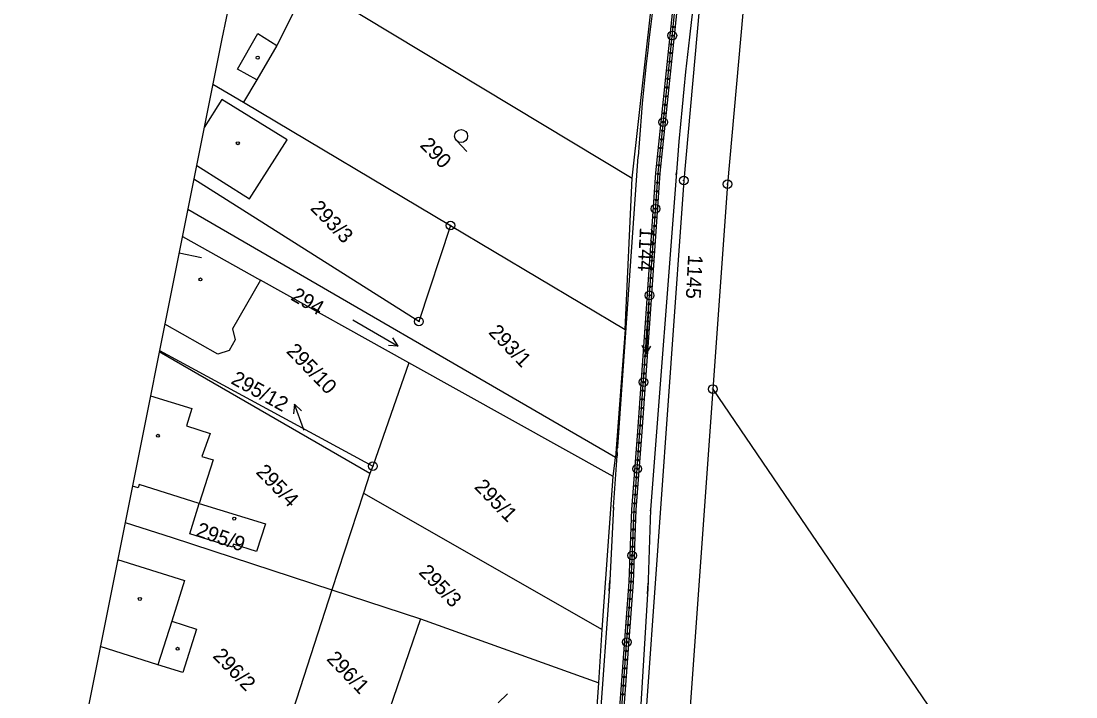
# Model space of a CAD drawing. Extents: x -548552 to -543113, y -1131925 to -1123599.
# Drawn here: x -547973.3 to -547852, y -1129232.9 to -1129155.2 of the extents above; entities that cross this region are included whole.
import ezdxf

# ---------------------------------------------------------------- set-up
doc = ezdxf.new("R2010")
doc.units = 0
for name, color, linetype in [('Hranice parcel', 7, 'Continuous'), ('Parcelní čísla', 7, 'Continuous'), ('Pop  PČ popisy', 7, 'Continuous'), ('Profile', 7, 'Continuous'), ('PROFILY NÁVRH', 7, 'Continuous'), ('STANIČENÍ', 7, 'Continuous'), ('Vnitřní kresba', 7, 'Continuous'), ('Značky bodu BP', 7, 'Continuous'), ('Značky budov', 7, 'Continuous'), ('Značky kultur', 7, 'Continuous')]:
    doc.layers.add(name, color=color, linetype=linetype)

msp = doc.modelspace()

# ---------------------------------------------------------------- linework, layer by layer
at = {"layer": 'Hranice parcel'}
for p, q in [((-547939.12, -1129151.47), (-547903.04, -1129173.24)), ((-547903.04, -1129173.24), (-547900.82, -1129153.33)), ((-547951.24, -1129162.42), (-547947.73, -1129164.51)), ((-547947.73, -1129164.51), (-547923.93, -1129178.68)), ((-547903.84, -1129190.64), (-547903.04, -1129173.24)), ((-547904.96, -1129205.36), (-547954.13, -1129176.84)), ((-547923.93, -1129178.68), (-547903.84, -1129190.64)), ((-547954.75, -1129179.95), (-547945.78, -1129184.96)), ((-547928.72, -1129194.48), (-547945.78, -1129184.96)), ((-547903.84, -1129190.64), (-547904.96, -1129205.36)), ((-547933.19, -1129207.21), (-547957.41, -1129193.21)), ((-547957.38, -1129193.07), (-547932.84, -1129206.37)), ((-547928.72, -1129194.48), (-547932.84, -1129206.37)), ((-547905.23, -1129207.58), (-547928.72, -1129194.48)), ((-547893.76, -1129197.5), (-547897.12, -1129244.73)), ((-547893.76, -1129197.5), (-547826.6, -1129296.2)), ((-547905.23, -1129207.58), (-547904.96, -1129205.36)), ((-547933.19, -1129207.21), (-547933.93, -1129209.49)), ((-547932.84, -1129206.37), (-547933.19, -1129207.21)), ((-547906.46, -1129225.18), (-547905.23, -1129207.58)), ((-547933.93, -1129209.49), (-547937.55, -1129220.62)), ((-547933.93, -1129209.49), (-547906.46, -1129225.18)), ((-547937.55, -1129220.62), (-547942.59, -1129236.09)), ((-547937.55, -1129220.62), (-547927.38, -1129223.94)), ((-547927.38, -1129223.94), (-547932.61, -1129239.25)), ((-547927.38, -1129223.94), (-547906.88, -1129231.29)), ((-547906.88, -1129231.29), (-547906.46, -1129225.18)), ((-547908.01, -1129247.43), (-547906.88, -1129231.29))]:
    msp.add_line(p, q, dxfattribs=at)
for points in [[(-547821.33, -1128991.6), (-547858.78, -1129039.17), (-547867.17, -1129050.77), (-547872.99, -1129060.45), (-547877.72, -1129073.44), (-547883.99, -1129099.45), (-547892.72, -1129136.3), (-547895.31, -1129153.82), (-547897.09, -1129173.51), (-547903.07, -1129257.59), (-547902.96, -1129283.35), (-547902.01, -1129301.23), (-547897.46, -1129348.86), (-547895.9, -1129389.55), (-547894.79, -1129408.16)], [(-547939.12, -1129151.47), (-547940.06, -1129153.08), (-547940.85, -1129152.69), (-547941.98, -1129154.19), (-547943.89, -1129157.99), (-547946.19, -1129161.91), (-547947.73, -1129164.51)], [(-547890.3, -1129154.24), (-547892.07, -1129173.92), (-547893.76, -1129197.5)], [(-547953.11, -1129171.77), (-547947.02, -1129175.61), (-547942.7, -1129168.84), (-547950.22, -1129164.18)], [(-547950.22, -1129164.18), (-547952.24, -1129167.4)], [(-547923.93, -1129178.68), (-547927.55, -1129189.72), (-547953.43, -1129173.36)], [(-547945.78, -1129184.96), (-547949.01, -1129190.57), (-547948.68, -1129191.83), (-547949.37, -1129193.06), (-547950.69, -1129193.48), (-547956.77, -1129190.03)], [(-547958.42, -1129198.27), (-547953.68, -1129199.75), (-547954.3, -1129201.73), (-547951.55, -1129202.61), (-547952.53, -1129205.25), (-547951.23, -1129205.66), (-547952.81, -1129210.67), (-547959.74, -1129208.5), (-547959.85, -1129208.86), (-547960.51, -1129208.66)], [(-547952.81, -1129210.67), (-547945.19, -1129213.01), (-547946.22, -1129216.19), (-547948.89, -1129215.35), (-547949.01, -1129215.69), (-547953.9, -1129214.17), (-547952.81, -1129210.67)], [(-547961.35, -1129212.85), (-547955.92, -1129214.57), (-547937.55, -1129220.62)], [(-547962.21, -1129217.13), (-547954.51, -1129219.54), (-547955.98, -1129224.22), (-547953.14, -1129225.11), (-547954.72, -1129230.13), (-547957.59, -1129229.22), (-547964.21, -1129227.14)]]:
    msp.add_lwpolyline(points, dxfattribs=at)
at = {"layer": 'Pop  PČ popisy'}
for p, q in [((-547941.86, -1129199.24), (-547941.98, -1129200.36)), ((-547940.83, -1129202.06), (-547941.86, -1129199.24)), ((-547941.86, -1129199.24), (-547941.04, -1129200.01)), ((-547940.77, -1129202.24), (-547940.83, -1129202.06))]:
    msp.add_line(p, q, dxfattribs=at)
at = {"layer": 'Profile'}
for p, q in [((-547908.26, -1128948), (-547950.2, -1129157.22)), ((-547927.09, -1129041.93), (-547950.2, -1129157.22)), ((-547950.2, -1129157.22), (-547973.3, -1129272.5)), ((-547950.2, -1129157.22), (-547973.3, -1129272.5)), ((-547952.55, -1129182.4), (-547955.14, -1129181.88))]:
    msp.add_line(p, q, dxfattribs=at)
at = {"layer": 'PROFILY NÁVRH'}
for p, q in [((-547900.3, -1129172.61), (-547897.15, -1129142.3)), ((-547899.81, -1129172.65), (-547896.66, -1129142.35)), ((-547904.69, -1129204.14), (-547902.35, -1129170.75)), ((-547897.81, -1129171.05), (-547900.91, -1129211.41)), ((-547901.42, -1129188.82), (-547900.3, -1129172.61)), ((-547900.92, -1129188.86), (-547899.81, -1129172.65)), ((-547902.38, -1129202.4), (-547901.42, -1129188.82)), ((-547901.89, -1129202.44), (-547900.92, -1129188.86)), ((-547903.06, -1129211.36), (-547902.38, -1129202.4)), ((-547902.56, -1129211.39), (-547901.89, -1129202.44)), ((-547904.69, -1129204.14), (-547904.81, -1129204.36)), ((-547904.81, -1129204.36), (-547904.76, -1129205.18)), ((-547905.18, -1129211.09), (-547904.76, -1129205.18)), ((-547905.18, -1129211.09), (-547905.65, -1129220.27)), ((-547903.39, -1129219.7), (-547903.06, -1129211.36)), ((-547902.89, -1129219.72), (-547902.56, -1129211.38)), ((-547900.91, -1129211.41), (-547901.23, -1129220.6)), ((-547905.65, -1129220.27), (-547907.87, -1129251.58)), ((-547905.74, -1129251.64), (-547903.39, -1129219.69)), ((-547905.24, -1129251.67), (-547902.89, -1129219.72)), ((-547901.22, -1129220.45), (-547903.12, -1129251.83))]:
    msp.add_line(p, q, dxfattribs=at)
msp.add_circle((-547900.06, -1129172.76), 0.1, dxfattribs=at)
for centre, radius, start, end in [((-547555, -1129197.42), 343.82, 164.8509, 175.6014), ((-547614.31, -1129190.95), 288.75, 166.2603, 175.9901)]:
    msp.add_arc(centre, radius, start, end, dxfattribs=at)
at = {"layer": 'STANIČENÍ'}
for p, q in [((-547900.05, -1129172.63), (-547896.9, -1129142.32)), ((-547902.47, -1129172.47), (-547902.45, -1129172.25)), ((-547901.17, -1129188.84), (-547900.05, -1129172.63)), ((-547897.95, -1129172.85), (-547897.92, -1129172.57)), ((-547902.14, -1129202.42), (-547901.17, -1129188.84)), ((-547902.81, -1129211.37), (-547902.14, -1129202.42)), ((-547905.19, -1129211.19), (-547905.16, -1129210.91)), ((-547903.14, -1129219.71), (-547902.81, -1129211.37)), ((-547900.92, -1129211.52), (-547900.9, -1129211.3)), ((-547905.68, -1129220.7), (-547905.59, -1129219.52)), ((-547905.49, -1129251.66), (-547903.14, -1129219.71)), ((-547901.26, -1129221.06), (-547901.17, -1129219.85))]:
    msp.add_line(p, q, dxfattribs=at)
for centre, radius in [((-547898.41, -1129156.84), 0.5), ((-547898.31, -1129155.85), 0.1), ((-547898.52, -1129157.84), 0.1), ((-547898.41, -1129156.84), 0.1), ((-547898.62, -1129158.83), 0.1), ((-547898.72, -1129159.83), 0.1), ((-547898.83, -1129160.82), 0.1), ((-547898.93, -1129161.82), 0.1), ((-547899.14, -1129163.81), 0.1), ((-547899.03, -1129162.81), 0.1), ((-547899.24, -1129164.8), 0.1), ((-547899.34, -1129165.79), 0.1), ((-547899.45, -1129166.79), 0.5), ((-547899.45, -1129166.79), 0.1), ((-547899.65, -1129168.78), 0.1), ((-547899.55, -1129167.78), 0.1), ((-547899.76, -1129169.77), 0.1), ((-547899.86, -1129170.77), 0.1), ((-547899.96, -1129171.76), 0.1), ((-547900.2, -1129174.75), 0.1), ((-547900.13, -1129173.76), 0.1), ((-547900.27, -1129175.75), 0.1), ((-547900.34, -1129176.75), 0.5), ((-547900.34, -1129176.75), 0.1), ((-547900.41, -1129177.75), 0.1), ((-547900.47, -1129178.74), 0.1), ((-547900.61, -1129180.74), 0.1), ((-547900.54, -1129179.74), 0.1), ((-547900.68, -1129181.74), 0.1), ((-547900.75, -1129182.73), 0.1), ((-547900.82, -1129183.73), 0.1), ((-547900.95, -1129185.73), 0.1), ((-547900.89, -1129184.73), 0.1), ((-547901.02, -1129186.72), 0.5), ((-547901.02, -1129186.72), 0.1), ((-547901.09, -1129187.72), 0.1), ((-547901.16, -1129188.72), 0.1), ((-547901.23, -1129189.72), 0.1), ((-547901.37, -1129191.71), 0.1), ((-547901.3, -1129190.71), 0.1), ((-547901.44, -1129192.71), 0.1), ((-547901.51, -1129193.71), 0.1), ((-547901.59, -1129194.7), 0.1), ((-547901.73, -1129196.7), 0.5), ((-547901.73, -1129196.7), 0.1), ((-547901.66, -1129195.7), 0.1), ((-547901.8, -1129197.7), 0.1), ((-547901.87, -1129198.69), 0.1), ((-547901.94, -1129199.69), 0.1), ((-547902.01, -1129200.69), 0.1), ((-547902.16, -1129202.68), 0.1), ((-547902.08, -1129201.69), 0.1), ((-547902.23, -1129203.68), 0.1), ((-547902.31, -1129204.68), 0.1), ((-547902.46, -1129206.67), 0.5), ((-547902.38, -1129205.68), 0.1), ((-547902.46, -1129206.67), 0.1), ((-547902.61, -1129208.67), 0.1), ((-547902.53, -1129207.67), 0.1), ((-547902.68, -1129209.66), 0.1), ((-547902.76, -1129210.66), 0.1), ((-547902.82, -1129211.66), 0.1), ((-547902.9, -1129213.66), 0.1), ((-547902.86, -1129212.66), 0.1), ((-547902.94, -1129214.66), 0.1), ((-547902.98, -1129215.65), 0.1), ((-547903.02, -1129216.65), 0.5), ((-547903.02, -1129216.65), 0.1), ((-547903.06, -1129217.65), 0.1), ((-547903.13, -1129219.65), 0.1), ((-547903.1, -1129218.65), 0.1), ((-547903.21, -1129220.65), 0.1), ((-547903.28, -1129221.65), 0.1), ((-547903.35, -1129222.64), 0.1), ((-547903.43, -1129223.64), 0.1), ((-547903.57, -1129225.63), 0.1), ((-547903.5, -1129224.64), 0.1), ((-547903.65, -1129226.63), 0.5), ((-547903.65, -1129226.63), 0.1), ((-547903.72, -1129227.63), 0.1), ((-547903.79, -1129228.63), 0.1), ((-547903.94, -1129230.62), 0.1), ((-547903.87, -1129229.62), 0.1), ((-547904.02, -1129231.62), 0.1), ((-547904.09, -1129232.62), 0.1)]:
    msp.add_circle(centre, radius, dxfattribs=at)
at = {"layer": 'Vnitřní kresba'}
for p, q in [((-547948.41, -1129160.71), (-547946.08, -1129156.61)), ((-547946.08, -1129156.61), (-547943.89, -1129157.99)), ((-547946.19, -1129161.91), (-547948.41, -1129160.71)), ((-547955.98, -1129224.22), (-547957.59, -1129229.22))]:
    msp.add_line(p, q, dxfattribs=at)
at = {"layer": 'Značky bodu BP'}
for centre, radius in [((-547897.09, -1129173.51), 0.5), ((-547897.09, -1129173.51), 0.0303), ((-547892.07, -1129173.92), 0.5), ((-547892.07, -1129173.92), 0.0303), ((-547923.93, -1129178.68), 0.5), ((-547923.93, -1129178.68), 0.0303), ((-547927.55, -1129189.72), 0.5), ((-547927.55, -1129189.72), 0.0303), ((-547893.76, -1129197.5), 0.5), ((-547893.76, -1129197.5), 0.0303), ((-547932.84, -1129206.37), 0.5), ((-547932.84, -1129206.37), 0.0303)]:
    msp.add_circle(centre, radius, dxfattribs=at)
at = {"layer": 'Značky budov'}
for centre in [(-547946.09, -1129159.38), (-547948.38, -1129169.22), (-547952.68, -1129184.89), (-547957.57, -1129202.88), (-547948.79, -1129212.41), (-547959.65, -1129221.65), (-547955.31, -1129227.38)]:
    msp.add_circle(centre, 0.175, dxfattribs=at)
at = {"layer": 'Značky kultur'}
for p, q in [((-547923.24, -1129168.91), (-547922.03, -1129170.17)), ((-547901.11, -1129187.51), (-547901.43, -1129193.5)), ((-547935.14, -1129189.55), (-547929.94, -1129192.55)), ((-547929.94, -1129192.55), (-547930.54, -1129191.62)), ((-547929.94, -1129192.55), (-547931.04, -1129192.49)), ((-547901.43, -1129193.5), (-547901.88, -1129192.5)), ((-547901.43, -1129193.5), (-547900.88, -1129192.55)), ((-547918.45, -1129233.62), (-547917.37, -1129232.58))]:
    msp.add_line(p, q, dxfattribs=at)
msp.add_circle((-547922.7, -1129168.39), 0.75, dxfattribs=at)

# ---------------------------------------------------------------- texts
at = {"layer": 'Parcelní čísla'}
for s, rotation, p in [('290', 313.9858, (-547927.52, -1129169.53)), ('293/3', 313.9858, (-547940.13, -1129176.77)), ('1144', 266.9858, (-547902.13, -1129178.86)), ('1145', 266.9858, (-547896.59, -1129182.03)), ('294', 329.9858, (-547942.39, -1129187.18)), ('293/1', 313.9858, (-547919.64, -1129191.05)), ('295/10', 313.9858, (-547942.89, -1129193.23)), ('295/12', 330.9858, (-547949.28, -1129196.8)), ('295/4', 313.9858, (-547946.39, -1129207.13)), ('295/1', 313.9858, (-547921.27, -1129208.84)), ('295/9', 340.9858, (-547953.29, -1129214.38)), ('295/3', 313.9858, (-547927.66, -1129218.66)), ('296/2', 313.9858, (-547951.35, -1129228.29)), ('296/1', 313.9858, (-547938.27, -1129228.63))]:
    msp.add_text(s, height=1.7, rotation=rotation, dxfattribs=at).set_placement(p)

doc.saveas('drawing.dxf')
